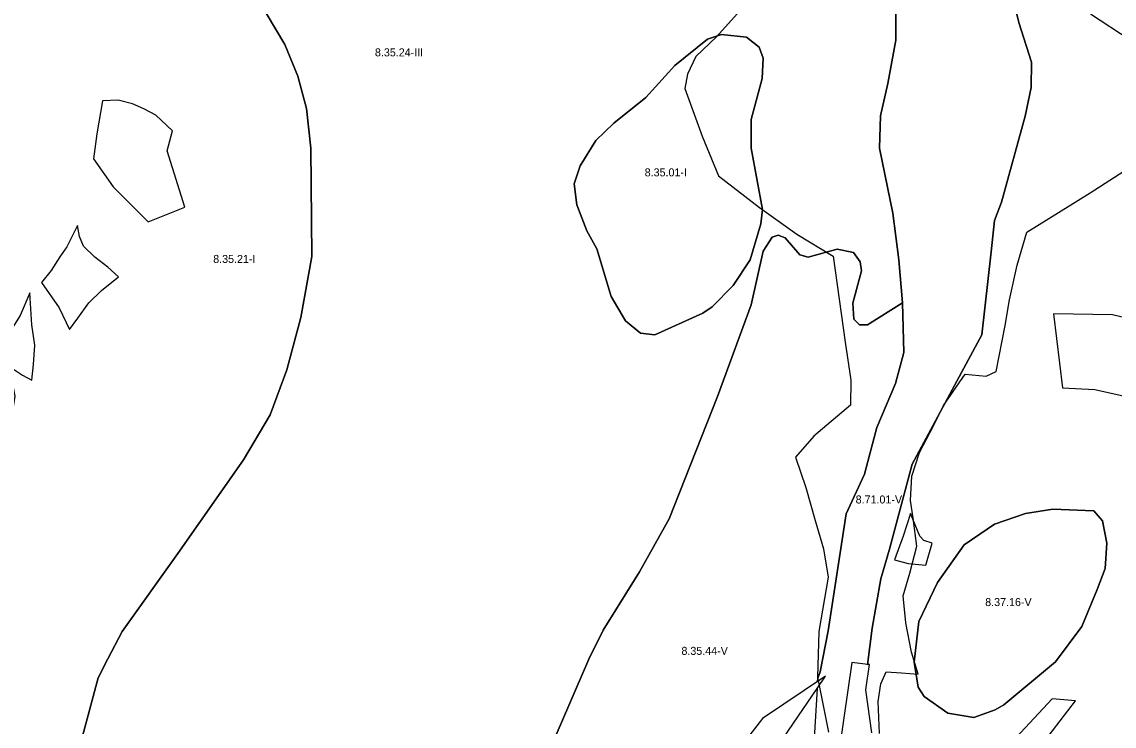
# Model space of a CAD drawing. Extents: x -547623 to -533936, y -1096714 to -1086523.
# Drawn here: x -542784 to -541420, y -1094116 to -1093236 of the extents above; entities that cross this region are included whole.
import ezdxf

# ---------------------------------------------------------------- set-up
doc = ezdxf.new("R2010")
doc.units = 0
for name, color, linetype in [('Vrstva 27', 7, 'Continuous'), ('Vrstva 28', 7, 'Continuous'), ('Vrstva 29', 7, 'Continuous')]:
    doc.layers.add(name, color=color, linetype=linetype)

msp = doc.modelspace()

# ---------------------------------------------------------------- linework, layer by layer
at = {"layer": 'Vrstva 28'}
for p, q in [((-541539, -1093237), (-541549.5, -1093192)), ((-541549.5, -1093192), (-541539, -1093237)), ((-542479, -1093225.5), (-542455.5, -1093264.5)), ((-542455.5, -1093264.5), (-542479, -1093225.5)), ((-541692.5, -1093218.5), (-541692.5, -1093259)), ((-541692.5, -1093259), (-541692.5, -1093218.5)), ((-541523, -1093286.5), (-541539, -1093237)), ((-541539, -1093237), (-541523, -1093286.5)), ((-541927.5, -1093258), (-541910, -1093252)), ((-541910, -1093252), (-541927.5, -1093258)), ((-541910, -1093252), (-541879, -1093255.5)), ((-541879, -1093255.5), (-541910, -1093252)), ((-542455.5, -1093264.5), (-542439.5, -1093304)), ((-542439.5, -1093304), (-542455.5, -1093264.5)), ((-541968.5, -1093290.5), (-541927.5, -1093258)), ((-541927.5, -1093258), (-541968.5, -1093290.5)), ((-541879, -1093255.5), (-541863, -1093268)), ((-541863, -1093268), (-541879, -1093255.5)), ((-541863, -1093268), (-541858, -1093281.5)), ((-541858, -1093281.5), (-541863, -1093268)), ((-541692.5, -1093259), (-541702.5, -1093313)), ((-541702.5, -1093313), (-541692.5, -1093259)), ((-541858, -1093281.5), (-541859.5, -1093307)), ((-541859.5, -1093307), (-541858, -1093281.5)), ((-542004.5, -1093330.5), (-541968.5, -1093290.5)), ((-541968.5, -1093290.5), (-542004.5, -1093330.5)), ((-541523.5, -1093318), (-541523, -1093286.5)), ((-541523, -1093286.5), (-541523.5, -1093318)), ((-542439.5, -1093304), (-542428.5, -1093344.5)), ((-542428.5, -1093344.5), (-542439.5, -1093304)), ((-541859.5, -1093307), (-541873, -1093358)), ((-541873, -1093358), (-541859.5, -1093307)), ((-541702.5, -1093313), (-541711.5, -1093353.5)), ((-541711.5, -1093353.5), (-541702.5, -1093313)), ((-541531, -1093354), (-541523.5, -1093318)), ((-541523.5, -1093318), (-541531, -1093354)), ((-542044.5, -1093362.5), (-542004.5, -1093330.5)), ((-542004.5, -1093330.5), (-542044.5, -1093362.5)), ((-542428.5, -1093344.5), (-542423, -1093394)), ((-542423, -1093394), (-542428.5, -1093344.5)), ((-542067, -1093384.5), (-542044.5, -1093362.5)), ((-542044.5, -1093362.5), (-542067, -1093384.5)), ((-541873, -1093358), (-541873, -1093394)), ((-541873, -1093394), (-541873, -1093358)), ((-541711.5, -1093353.5), (-541713, -1093394)), ((-541713, -1093394), (-541711.5, -1093353.5)), ((-541560.5, -1093461.5), (-541531, -1093354)), ((-541531, -1093354), (-541560.5, -1093461.5)), ((-542086.5, -1093416), (-542067, -1093384.5)), ((-542067, -1093384.5), (-542086.5, -1093416)), ((-542423, -1093394), (-542422, -1093529)), ((-542422, -1093529), (-542423, -1093394)), ((-541873, -1093394), (-541859, -1093470.5)), ((-541859, -1093470.5), (-541873, -1093394)), ((-541713, -1093394), (-541696, -1093475)), ((-541696, -1093475), (-541713, -1093394)), ((-542094, -1093438.5), (-542086.5, -1093416)), ((-542086.5, -1093416), (-542094, -1093438.5)), ((-542091, -1093464.5), (-542094, -1093438.5)), ((-542094, -1093438.5), (-542091, -1093464.5)), ((-542078.5, -1093497), (-542091, -1093464.5)), ((-542091, -1093464.5), (-542078.5, -1093497)), ((-541859, -1093470.5), (-541861, -1093488.5)), ((-541861, -1093488.5), (-541859, -1093470.5)), ((-541569, -1093484), (-541560.5, -1093461.5)), ((-541560.5, -1093461.5), (-541569, -1093484)), ((-541696, -1093475), (-541688.5, -1093533.5)), ((-541688.5, -1093533.5), (-541696, -1093475)), ((-541573.5, -1093523.5), (-541569, -1093484)), ((-541569, -1093484), (-541573.5, -1093523.5)), ((-542066, -1093519.5), (-542078.5, -1093497)), ((-542078.5, -1093497), (-542066, -1093519.5)), ((-541861, -1093488.5), (-541874.5, -1093533.5)), ((-541874.5, -1093533.5), (-541861, -1093488.5)), ((-541847, -1093505), (-541858, -1093522.5)), ((-541858, -1093522.5), (-541847, -1093505)), ((-541839.5, -1093502.5), (-541847, -1093505)), ((-541847, -1093505), (-541839.5, -1093502.5)), ((-541830.5, -1093506), (-541839.5, -1093502.5)), ((-541839.5, -1093502.5), (-541830.5, -1093506)), ((-541812.5, -1093527), (-541830.5, -1093506)), ((-541830.5, -1093506), (-541812.5, -1093527)), ((-542048, -1093579), (-542066, -1093519.5)), ((-542066, -1093519.5), (-542048, -1093579)), ((-541858, -1093522.5), (-541873, -1093589.5)), ((-541873, -1093589.5), (-541858, -1093522.5)), ((-541802, -1093530), (-541812.5, -1093527)), ((-541812.5, -1093527), (-541802, -1093530)), ((-541765.5, -1093520), (-541802, -1093530)), ((-541802, -1093530), (-541765.5, -1093520)), ((-541745.5, -1093524), (-541765.5, -1093520)), ((-541765.5, -1093520), (-541745.5, -1093524)), ((-541737, -1093536), (-541745.5, -1093524)), ((-541745.5, -1093524), (-541737, -1093536)), ((-541585, -1093627), (-541573.5, -1093523.5)), ((-541573.5, -1093523.5), (-541585, -1093627)), ((-542422, -1093529), (-542435.5, -1093605.5)), ((-542435.5, -1093605.5), (-542422, -1093529)), ((-541874.5, -1093533.5), (-541895.5, -1093565.5)), ((-541895.5, -1093565.5), (-541874.5, -1093533.5)), ((-541735.5, -1093547), (-541737, -1093536)), ((-541737, -1093536), (-541735.5, -1093547)), ((-541688.5, -1093533.5), (-541684, -1093587)), ((-541684, -1093587), (-541688.5, -1093533.5)), ((-541746, -1093587.5), (-541735.5, -1093547)), ((-541735.5, -1093547), (-541746, -1093587.5)), ((-541895.5, -1093565.5), (-541922, -1093592)), ((-541922, -1093592), (-541895.5, -1093565.5)), ((-542030, -1093609.5), (-542048, -1093579)), ((-542048, -1093579), (-542030, -1093609.5)), ((-541922, -1093592), (-541933.5, -1093600)), ((-541933.5, -1093600), (-541922, -1093592)), ((-541873, -1093589.5), (-541915, -1093704)), ((-541915, -1093704), (-541873, -1093589.5)), ((-541745, -1093607.5), (-541746, -1093587.5)), ((-541746, -1093587.5), (-541745, -1093607.5)), ((-541684, -1093587), (-541728, -1093614.5)), ((-541728, -1093614.5), (-541684, -1093587)), ((-541684, -1093587), (-541682.5, -1093649)), ((-541682.5, -1093649), (-541684, -1093587)), ((-542435.5, -1093605.5), (-542453, -1093670.5)), ((-542453, -1093670.5), (-542435.5, -1093605.5)), ((-542011.5, -1093625), (-542030, -1093609.5)), ((-542030, -1093609.5), (-542011.5, -1093625)), ((-541933.5, -1093600), (-541993.5, -1093627)), ((-541993.5, -1093627), (-541933.5, -1093600)), ((-541738, -1093614.5), (-541745, -1093607.5)), ((-541745, -1093607.5), (-541738, -1093614.5)), ((-541728, -1093614.5), (-541738, -1093614.5)), ((-541738, -1093614.5), (-541728, -1093614.5)), ((-541993.5, -1093627), (-542011.5, -1093625)), ((-542011.5, -1093625), (-541993.5, -1093627)), ((-541604.5, -1093663), (-541585, -1093627)), ((-541585, -1093627), (-541604.5, -1093663)), ((-541682.5, -1093649), (-541693, -1093687.5)), ((-541693, -1093687.5), (-541682.5, -1093649)), ((-541672, -1093788.5), (-541604.5, -1093663)), ((-541604.5, -1093663), (-541672, -1093788.5)), ((-542453, -1093670.5), (-542474, -1093727)), ((-542474, -1093727), (-542453, -1093670.5)), ((-541693, -1093687.5), (-541716, -1093742.5)), ((-541716, -1093742.5), (-541693, -1093687.5)), ((-541915, -1093704), (-541975.5, -1093856.5)), ((-541975.5, -1093856.5), (-541915, -1093704)), ((-542474, -1093727), (-542507, -1093783)), ((-542507, -1093783), (-542474, -1093727)), ((-541716, -1093742.5), (-541725.5, -1093777)), ((-541725.5, -1093777), (-541716, -1093742.5)), ((-542507, -1093783), (-542589, -1093900)), ((-542589, -1093900), (-542507, -1093783)), ((-541725.5, -1093777), (-541731.5, -1093801)), ((-541731.5, -1093801), (-541725.5, -1093777)), ((-541731.5, -1093801), (-541754.5, -1093850.5)), ((-541754.5, -1093850.5), (-541731.5, -1093801)), ((-541700.5, -1093894.5), (-541672, -1093788.5)), ((-541672, -1093788.5), (-541700.5, -1093894.5)), ((-541754.5, -1093850.5), (-541777, -1093996.5)), ((-541777, -1093996.5), (-541754.5, -1093850.5)), ((-541530.5, -1093850), (-541569, -1093863.5)), ((-541569, -1093863.5), (-541530.5, -1093850)), ((-541496.5, -1093844.5), (-541530.5, -1093850)), ((-541530.5, -1093850), (-541496.5, -1093844.5)), ((-541445, -1093846.5), (-541496.5, -1093844.5)), ((-541496.5, -1093844.5), (-541445, -1093846.5)), ((-541434.5, -1093859), (-541445, -1093846.5)), ((-541445, -1093846.5), (-541434.5, -1093859)), ((-541975.5, -1093856.5), (-542012.5, -1093923)), ((-542012.5, -1093923), (-541975.5, -1093856.5)), ((-541569, -1093863.5), (-541607, -1093889)), ((-541607, -1093889), (-541569, -1093863.5)), ((-541429, -1093887), (-541434.5, -1093859)), ((-541434.5, -1093859), (-541429, -1093887)), ((-541711, -1093931.5), (-541700.5, -1093894.5)), ((-541700.5, -1093894.5), (-541711, -1093931.5)), ((-541607, -1093889), (-541640.5, -1093936)), ((-541640.5, -1093936), (-541607, -1093889)), ((-541431, -1093918.5), (-541429, -1093887)), ((-541429, -1093887), (-541431, -1093918.5)), ((-542589, -1093900), (-542658.5, -1093997.5)), ((-542658.5, -1093997.5), (-542589, -1093900)), ((-542012.5, -1093923), (-542058, -1093995.5)), ((-542058, -1093995.5), (-542012.5, -1093923)), ((-541441, -1093945), (-541431, -1093918.5)), ((-541431, -1093918.5), (-541441, -1093945)), ((-541722, -1093993), (-541711, -1093931.5)), ((-541711, -1093931.5), (-541722, -1093993)), ((-541640.5, -1093936), (-541663.5, -1093985)), ((-541663.5, -1093985), (-541640.5, -1093936)), ((-541460, -1093991), (-541441, -1093945)), ((-541441, -1093945), (-541460, -1093991)), ((-541663.5, -1093985), (-541669.5, -1094035.5)), ((-541669.5, -1094035.5), (-541663.5, -1093985)), ((-541493, -1094035), (-541460, -1093991)), ((-541460, -1093991), (-541493, -1094035)), ((-542658.5, -1093997.5), (-542676.5, -1094031.5)), ((-542676.5, -1094031.5), (-542658.5, -1093997.5)), ((-542058, -1093995.5), (-542076, -1094032)), ((-542076, -1094032), (-542058, -1093995.5)), ((-541777, -1093996.5), (-541787, -1094047.5)), ((-541787, -1094047.5), (-541777, -1093996.5)), ((-541727.7, -1094039), (-541722, -1093993)), ((-541722, -1093993), (-541727.7, -1094039)), ((-542676.5, -1094031.5), (-542688.5, -1094055)), ((-542688.5, -1094055), (-542676.5, -1094031.5)), ((-542076, -1094032), (-542116.5, -1094126.5)), ((-542116.5, -1094126.5), (-542076, -1094032)), ((-541669.5, -1094035.5), (-541664.5, -1094067)), ((-541664.5, -1094067), (-541669.5, -1094035.5)), ((-541557.5, -1094089), (-541493, -1094035)), ((-541493, -1094035), (-541557.5, -1094089)), ((-542688.5, -1094055), (-542708.5, -1094129.5)), ((-542708.5, -1094129.5), (-542688.5, -1094055)), ((-541790.3, -1094059.7), (-541790, -1094055.5)), ((-541790, -1094055.5), (-541790.2, -1094058.7)), ((-541790, -1094055.5), (-541787, -1094047.5)), ((-541787, -1094047.5), (-541790, -1094055.5)), ((-541790.8, -1094068.4), (-541794.5, -1094130.5)), ((-541664.5, -1094067), (-541657, -1094078.5)), ((-541657, -1094078.5), (-541664.5, -1094067)), ((-541657, -1094078.5), (-541627.5, -1094099.5)), ((-541627.5, -1094099.5), (-541657, -1094078.5)), ((-541627.5, -1094099.5), (-541595, -1094104.5)), ((-541595, -1094104.5), (-541627.5, -1094099.5)), ((-541595, -1094104.5), (-541568.5, -1094095)), ((-541568.5, -1094095), (-541595, -1094104.5)), ((-541568.5, -1094095), (-541557.5, -1094089)), ((-541557.5, -1094089), (-541568.5, -1094095))]:
    msp.add_line(p, q, dxfattribs=at)
for points in [[(-541549.5, -1093192), (-541539, -1093237), (-541523, -1093286.5), (-541523.5, -1093318), (-541531, -1093354), (-541560.5, -1093461.5), (-541569, -1093484), (-541573.5, -1093523.5), (-541585, -1093627), (-541604.5, -1093663), (-541672, -1093788.5), (-541700.5, -1093894.5), (-541711, -1093931.5), (-541722, -1093993), (-541727.7, -1094039)], [(-541560.5, -1093461.5), (-541531, -1093354), (-541523.5, -1093318), (-541523, -1093286.5), (-541539, -1093237), (-541549.5, -1093192)], [(-542479, -1093225.5), (-542455.5, -1093264.5), (-542439.5, -1093304), (-542428.5, -1093344.5), (-542423, -1093394), (-542422, -1093529), (-542435.5, -1093605.5), (-542453, -1093670.5), (-542474, -1093727), (-542507, -1093783), (-542589, -1093900), (-542658.5, -1093997.5), (-542676.5, -1094031.5), (-542688.5, -1094055), (-542708.5, -1094129.5)], [(-541858, -1093522.5), (-541847, -1093505), (-541839.5, -1093502.5), (-541830.5, -1093506), (-541812.5, -1093527), (-541802, -1093530), (-541765.5, -1093520), (-541745.5, -1093524), (-541737, -1093536), (-541735.5, -1093547), (-541746, -1093587.5), (-541745, -1093607.5), (-541738, -1093614.5), (-541728, -1093614.5), (-541684, -1093587), (-541688.5, -1093533.5), (-541696, -1093475), (-541713, -1093394), (-541711.5, -1093353.5), (-541702.5, -1093313), (-541692.5, -1093259), (-541692.5, -1093218.5)], [(-541692.5, -1093218.5), (-541692.5, -1093259), (-541702.5, -1093313), (-541711.5, -1093353.5), (-541713, -1093394), (-541696, -1093475), (-541688.5, -1093533.5), (-541684, -1093587), (-541682.5, -1093649), (-541693, -1093687.5), (-541716, -1093742.5), (-541725.5, -1093777), (-541731.5, -1093801), (-541754.5, -1093850.5), (-541777, -1093996.5), (-541787, -1094047.5), (-541790, -1094055.5), (-541790.2, -1094058.7)], [(-542044.5, -1093362.5), (-542067, -1093384.5), (-542086.5, -1093416), (-542094, -1093438.5), (-542091, -1093464.5), (-542078.5, -1093497), (-542066, -1093519.5), (-542048, -1093579), (-542030, -1093609.5), (-542011.5, -1093625), (-541993.5, -1093627), (-541933.5, -1093600), (-541922, -1093592), (-541895.5, -1093565.5), (-541874.5, -1093533.5), (-541861, -1093488.5), (-541859, -1093470.5), (-541873, -1093394), (-541873, -1093358), (-541859.5, -1093307), (-541858, -1093281.5), (-541863, -1093268), (-541879, -1093255.5), (-541910, -1093252), (-541927.5, -1093258), (-541968.5, -1093290.5), (-542004.5, -1093330.5), (-542044.5, -1093362.5)], [(-541933.5, -1093600), (-541993.5, -1093627), (-542011.5, -1093625), (-542030, -1093609.5), (-542048, -1093579), (-542066, -1093519.5), (-542078.5, -1093497), (-542091, -1093464.5), (-542094, -1093438.5), (-542086.5, -1093416), (-542067, -1093384.5), (-542044.5, -1093362.5), (-542004.5, -1093330.5), (-541968.5, -1093290.5), (-541927.5, -1093258), (-541910, -1093252), (-541879, -1093255.5), (-541863, -1093268), (-541858, -1093281.5), (-541859.5, -1093307), (-541873, -1093358), (-541873, -1093394), (-541859, -1093470.5), (-541861, -1093488.5), (-541874.5, -1093533.5), (-541895.5, -1093565.5), (-541922, -1093592), (-541933.5, -1093600)], [(-541727.7, -1094039), (-541722, -1093993), (-541711, -1093931.5), (-541700.5, -1093894.5), (-541672, -1093788.5), (-541604.5, -1093663), (-541585, -1093627), (-541573.5, -1093523.5), (-541569, -1093484), (-541560.5, -1093461.5)], [(-542116.5, -1094126.5), (-542076, -1094032), (-542058, -1093995.5), (-542012.5, -1093923), (-541975.5, -1093856.5), (-541915, -1093704), (-541873, -1093589.5), (-541858, -1093522.5)], [(-541683.2, -1093878.2), (-541694, -1093907.7), (-541677.2, -1093912.6), (-541654.9, -1093914.6), (-541647.1, -1093887.1), (-541657.3, -1093883.8), (-541662.5, -1093878.5), (-541674.3, -1093849.9), (-541683.2, -1093878.2)], [(-541568.5, -1094095), (-541595, -1094104.5), (-541627.5, -1094099.5), (-541657, -1094078.5), (-541664.5, -1094067), (-541669.5, -1094035.5), (-541663.5, -1093985), (-541640.5, -1093936), (-541607, -1093889), (-541569, -1093863.5), (-541530.5, -1093850), (-541496.5, -1093844.5), (-541445, -1093846.5), (-541434.5, -1093859), (-541429, -1093887), (-541431, -1093918.5), (-541441, -1093945), (-541460, -1093991), (-541493, -1094035), (-541557.5, -1094089), (-541568.5, -1094095)], [(-541557.5, -1094089), (-541493, -1094035), (-541460, -1093991), (-541441, -1093945), (-541431, -1093918.5), (-541429, -1093887), (-541434.5, -1093859), (-541445, -1093846.5), (-541496.5, -1093844.5), (-541530.5, -1093850), (-541569, -1093863.5), (-541607, -1093889), (-541640.5, -1093936), (-541663.5, -1093985), (-541669.5, -1094035.5), (-541664.5, -1094067), (-541657, -1094078.5), (-541627.5, -1094099.5), (-541595, -1094104.5), (-541568.5, -1094095), (-541557.5, -1094089)], [(-541722.5, -1094123.8), (-541729.7, -1094070.2), (-541725.3, -1094038.7), (-541727.6, -1094038.4), (-541727.7, -1094039), (-541727.6, -1094038.4), (-541747.2, -1094036), (-541767.5, -1094174.4)], [(-541790.8, -1094068.4), (-541780.3, -1094053.1), (-541858.9, -1094105.9), (-541935.8, -1094205.5), (-541892.7, -1094217.8), (-541790.8, -1094068.4), (-541790.8, -1094068.4)], [(-541515.8, -1094146.5), (-541468, -1094083.7), (-541497.3, -1094081.4), (-541553.4, -1094141.9)]]:
    msp.add_lwpolyline(points, dxfattribs=at)
at = {"layer": 'Vrstva 29'}
for points in [[(-541890.4, -1093226.3), (-541916.5, -1093254.9), (-541942.2, -1093279.5), (-541952.8, -1093301.7), (-541955.8, -1093319.5), (-541934.4, -1093379), (-541914, -1093428.3), (-541862.7, -1093467.9), (-541816.2, -1093501.4), (-541770.6, -1093528.9), (-541755.7, -1093636.3), (-541748.6, -1093683.7), (-541748.9, -1093714.7), (-541794.9, -1093753.5), (-541817.9, -1093779.6), (-541804.9, -1093817.4), (-541793.1, -1093858.9), (-541782.6, -1093894.1), (-541777, -1093929.5), (-541788.5, -1093997.4), (-541790.2, -1094054.2), (-541776.4, -1094122.9)], [(-541399.9, -1093259.2), (-541449.4, -1093226.7)], [(-542580.4, -1093467.6), (-542602.4, -1093397.1), (-542595.9, -1093372.2), (-542616.5, -1093352.5), (-542631.5, -1093344.7), (-542645.7, -1093338.6), (-542663.8, -1093333.8), (-542683.4, -1093334.7), (-542690.5, -1093376), (-542694.6, -1093407.3), (-542669.8, -1093442.2), (-542626.2, -1093485.7), (-542580.4, -1093467.6)], [(-541713, -1094124.7), (-541714.3, -1094084.7), (-541711.2, -1094062.6), (-541704.4, -1094047.6), (-541685.3, -1094049.1), (-541664.5, -1094050.4), (-541672.8, -1094023.1), (-541680, -1093986.5), (-541683.2, -1093952.6), (-541675.1, -1093924.5), (-541666, -1093890.9), (-541670.9, -1093855.8), (-541674.1, -1093833.7), (-541672.3, -1093803.4), (-541662.9, -1093773.7), (-541645.5, -1093740.5), (-541632.7, -1093715), (-541605.7, -1093676.2), (-541579.6, -1093678.6), (-541567.2, -1093672.8), (-541555.8, -1093615.3), (-541550.5, -1093583.4), (-541540.9, -1093539.9), (-541529, -1093498.7), (-541449.7, -1093449.7), (-541388.8, -1093410.5)], [(-542714.1, -1093606.2), (-542700.5, -1093587.2), (-542684.7, -1093571.7), (-542663.1, -1093554.4), (-542676.4, -1093542.4), (-542692.7, -1093530.1), (-542707.1, -1093516.3), (-542711.9, -1093504.2), (-542714.5, -1093490.4), (-542727.9, -1093517.1), (-542736.4, -1093529.5), (-542747.5, -1093546.7), (-542759.4, -1093561.6), (-542737.5, -1093593.4), (-542724.6, -1093620.4), (-542714.1, -1093606.2)], [(-542769.3, -1093663.9), (-542767.9, -1093639.8), (-542771.5, -1093614.5), (-542774.1, -1093574.5), (-542785.9, -1093603), (-542812.7, -1093644.6), (-542832.6, -1093662.2), (-542858.9, -1093685.9), (-542838.2, -1093713.8), (-542824.9, -1093737), (-542803.2, -1093759.1), (-542796.9, -1093732.1), (-542792.5, -1093703.7), (-542799.5, -1093666.3), (-542783.3, -1093677.3), (-542771.6, -1093683.4), (-542769.3, -1093663.9)], [(-541390.3, -1093609.3), (-541422, -1093602), (-541495.3, -1093600.7), (-541484.2, -1093693.3), (-541443.7, -1093695.2), (-541380.8, -1093709.5)]]:
    msp.add_lwpolyline(points, dxfattribs=at)

# ---------------------------------------------------------------- texts
at = {"layer": 'Vrstva 27'}
for s, p in [('8.35.24-III', (-542343, -1093279.3)), ('8.35.01-I', (-542006.1, -1093429.1)), ('8.35.21-I', (-542545, -1093537.2)), ('8.71.01-V', (-541742.6, -1093837.5)), ('8.37.16-V', (-541580.8, -1093965.6)), ('8.35.44-V', (-541960.2, -1094026.5))]:
    msp.add_text(s, height=10, dxfattribs=at).set_placement(p)

doc.saveas('drawing.dxf')
